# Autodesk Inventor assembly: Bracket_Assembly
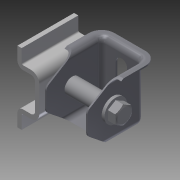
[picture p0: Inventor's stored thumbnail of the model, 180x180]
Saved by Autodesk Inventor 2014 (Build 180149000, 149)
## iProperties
Created: 2004-07
Part Number: Bracket_Assembly
Document SubType Name: Assembly
Designer: leeha
Manufacturer: Standard
Standards Organization: Custom
Mass: 823.539 g
Surface Area: 812.233 cm^2
Volume: 142.126 cm^3
Density: 5.79442 g/cm^3
Author: leeha
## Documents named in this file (7)
- C:\Users\iTools\Desktop\tutorial files\Assembly FEA 2\Bracket_Assembly.iam
- C:\Users\iTools\Desktop\tutorial files\Assembly FEA 2\Bracket.ipt
- C:\Users\iTools\Desktop\tutorial files\Assembly FEA 2\Mount.ipt
- C:\Users\iTools\Desktop\tutorial files\Assembly FEA 2\Sleeve.ipt
- C:\Users\iTools\Desktop\tutorial files\Assembly FEA 2\Bolt.ipt
- C:\Users\iTools\Desktop\tutorial files\Assembly FEA 2\Washer.ipt
- C:\Users\iTools\Desktop\tutorial files\Assembly FEA 2\Nut.ipt
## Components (8 placed, 6 different names)
1. Mount:1 — Mate:7, Mate:8, Mate:12, Angle:1
2. Bracket:1 — Mate:1, Mate:2, Mate:3, Mate:4, Mate:5, Mate:6, Mate:8, Mate:9, Angle:1
3. Sleeve:1 — Mate:1, Mate:2
4. Bolt:1 — Mate:9, Mate:10, Mate:11, Mate:13
5. Washer:1 — Mate:11, Mate:12, Mate:14
6. Washer:2 — Mate:3, Mate:4, Mate:10
7. Washer:3 — Mate:5, Mate:6, Mate:7
8. Nut:1 — Mate:13, Mate:14
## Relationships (15: Mate 14, Angle 1)
- Mate:1: Bracket:1 ↔ Sleeve:1
- Mate:2: Bracket:1 ↔ Sleeve:1
- Mate:3: Bracket:1 ↔ Washer:2
- Mate:4: Bracket:1 ↔ Washer:2
- Mate:5: Bracket:1 ↔ Washer:3
- Mate:6: Bracket:1 ↔ Washer:3
- Mate:7: Mount:1 ↔ Washer:3
- Mate:8: Mount:1 ↔ Bracket:1
- Mate:9: Bracket:1 ↔ Bolt:1
- Mate:10: Bolt:1 ↔ Washer:2
- Mate:11: Bolt:1 ↔ Washer:1
- Mate:12: Mount:1 ↔ Washer:1
- Mate:13: Bolt:1 ↔ Nut:1
- Mate:14: Washer:1 ↔ Nut:1
- Angle:1: Mount:1 ↔ Bracket:1
